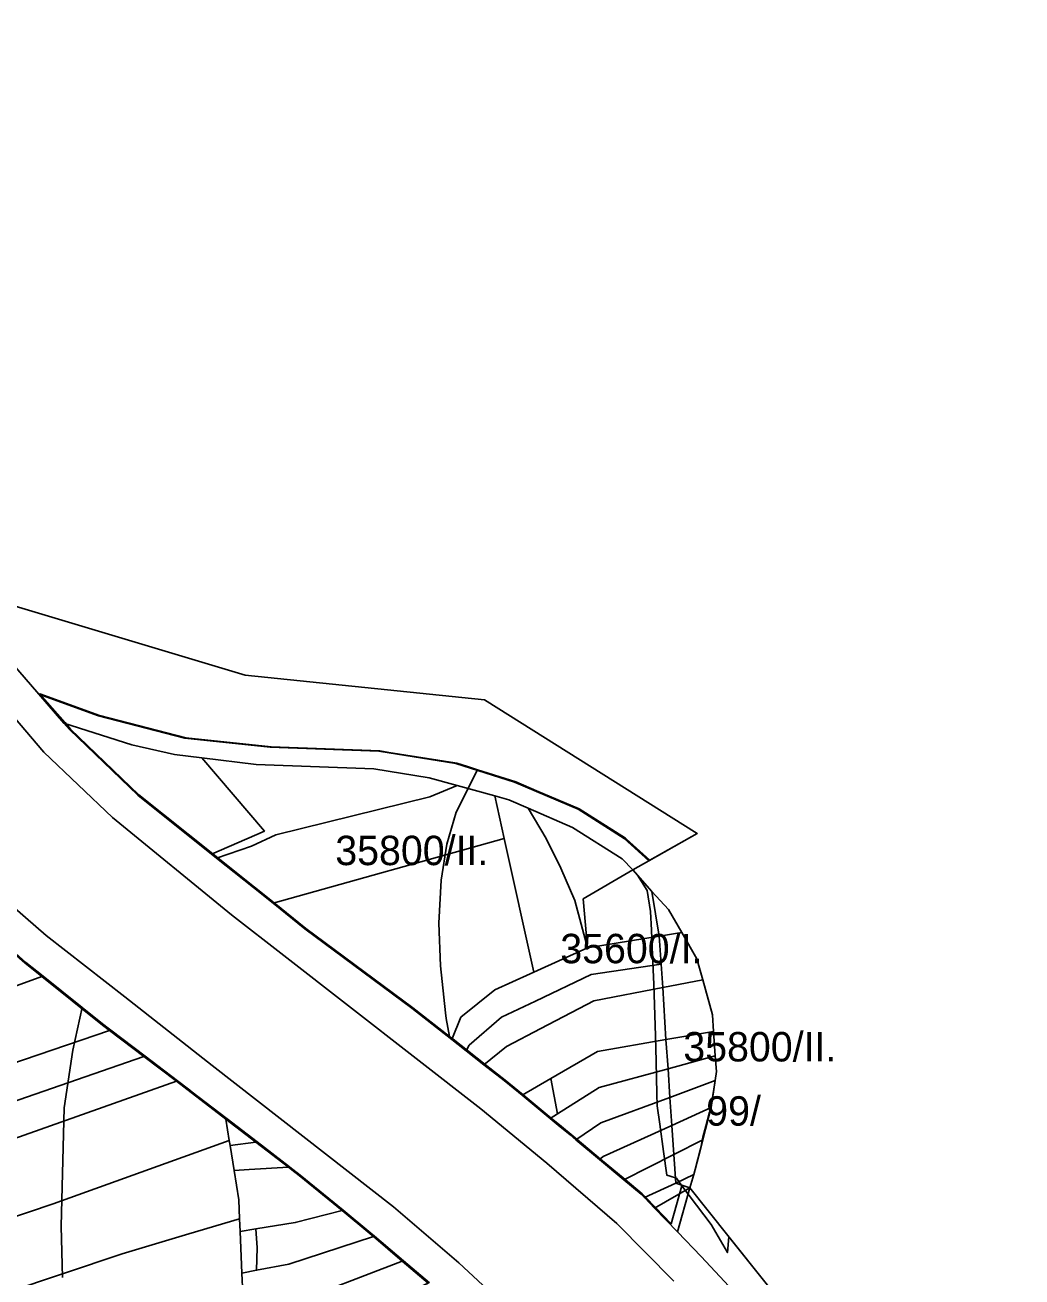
# Model space of a CAD drawing. Extents: x -535894 to -532827, y -1165802 to -1163635.
# Drawn here: x -533625 to -533117, y -1164507 to -1163869 of the extents above; entities that cross this region are included whole.
import ezdxf

# ---------------------------------------------------------------- set-up
doc = ezdxf.new("R2010")
doc.units = 0
for name, color, linetype in [('BPEJ_s', 7, 'Continuous'), ('orna_s', 7, 'Continuous'), ('ostatni_s', 7, 'Continuous'), ('trav_porost_s', 7, 'Continuous'), ('voda_s', 7, 'Continuous')]:
    doc.layers.add(name, color=color, linetype=linetype)

msp = doc.modelspace()

# ---------------------------------------------------------------- linework, layer by layer
at = {"layer": 'BPEJ_s'}
for points in [[(-533637.25, -1164163.31), (-533513.14, -1164200.59), (-533391.15, -1164213.21), (-533282.63, -1164281.27), (-533306.824, -1164294.927), (-533318.689, -1164284.23), (-533319.215, -1164283.756), (-533342.741, -1164268.774), (-533364.507, -1164259.557), (-533375.189, -1164255.034), (-533394.693, -1164248.828), (-533399.775, -1164247.211), (-533405.147, -1164245.502), (-533406.3, -1164245.318), (-533439.891, -1164239.947), (-533444.45, -1164239.218), (-533499.877, -1164237.155), (-533543.375, -1164232.587), (-533587.465, -1164221.122), (-533617.855, -1164210.054), (-533605.015, -1164224.773), (-533602.168, -1164228.037), (-533567.381, -1164261.637), (-533529.675, -1164291.688), (-533508.391, -1164308.653), (-533498.372, -1164316.72), (-533482.183, -1164329.739), (-533427.582, -1164370.261), (-533408.962, -1164384.837), (-533407.119, -1164386.28), (-533399.797, -1164392.005), (-533390.783, -1164399.064), (-533382.023, -1164405.923), (-533380.51, -1164407.108), (-533371.36, -1164414.666), (-533357.069, -1164426.477), (-533351.871, -1164430.767), (-533346.896, -1164434.883), (-533343.848, -1164437.415), (-533331.897, -1164447.377), (-533319.421, -1164457.779), (-533310.674, -1164465.071), (-533308.987, -1164466.818), (-533303.773, -1164472.227), (-533295.97, -1164480.319), (-533290.471, -1164460.99), (-533275.469, -1164480.798), (-533267.177, -1164495.052), (-533266.414, -1164486.957), (-533227.22, -1164536.15)], [(-533631.849, -1164340.954), (-533624.977, -1164347.111), (-533616.237, -1164354.099), (-533596.317, -1164370.019)], [(-533419.163, -1164510.425), (-533432.421, -1164499.181), (-533447.139, -1164486.688), (-533449.061, -1164485.066), (-533463.157, -1164473.487), (-533485.08, -1164455.484), (-533488.779, -1164452.648), (-533490.512, -1164451.319), (-533507.067, -1164438.601), (-533522.39, -1164426.846), (-533540.189, -1164413.195), (-533541.383, -1164412.285), (-533547.683, -1164407.482), (-533564.22, -1164394.878), (-533581.704, -1164381.564), (-533583.679, -1164380.059), (-533585.293, -1164378.83), (-533596.317, -1164370.019), (-533616.237, -1164354.099), (-533624.977, -1164347.111), (-533631.849, -1164340.954)], [(-533596.317, -1164370.019), (-533601.09, -1164391.8), (-533605.391, -1164421.259), (-533606.98, -1164481.63), (-533606.34, -1164507.75)], [(-533606.34, -1164507.75), (-533606.98, -1164481.63), (-533605.391, -1164421.259), (-533601.09, -1164391.8), (-533596.317, -1164370.019), (-533585.293, -1164378.83), (-533583.679, -1164380.059), (-533581.704, -1164381.564), (-533564.22, -1164394.878), (-533547.683, -1164407.482), (-533541.383, -1164412.285), (-533540.189, -1164413.195), (-533522.39, -1164426.846), (-533507.067, -1164438.601), (-533490.512, -1164451.319), (-533488.779, -1164452.648), (-533485.08, -1164455.484), (-533463.157, -1164473.487), (-533449.061, -1164485.066), (-533447.139, -1164486.688), (-533432.421, -1164499.181), (-533419.163, -1164510.425)]]:
    msp.add_lwpolyline(points, dxfattribs=at)
for points in [[(-533394.693, -1164248.828), (-533405.49, -1164270.43), (-533410.27, -1164286.67), (-533413.14, -1164305.15), (-533414.411, -1164326.97), (-533413.524, -1164348.809), (-533410.92, -1164372.686), (-533410.59, -1164375.71), (-533408.962, -1164384.837), (-533427.582, -1164370.261), (-533482.183, -1164329.739), (-533498.372, -1164316.72), (-533508.391, -1164308.653), (-533529.675, -1164291.688), (-533567.381, -1164261.637), (-533602.168, -1164228.037), (-533605.015, -1164224.773), (-533617.855, -1164210.054), (-533587.465, -1164221.122), (-533543.375, -1164232.587), (-533499.877, -1164237.155), (-533444.45, -1164239.218), (-533439.891, -1164239.947), (-533406.3, -1164245.318), (-533405.147, -1164245.502), (-533399.775, -1164247.211)], [(-533306.824, -1164294.927), (-533307.29, -1164295.19), (-533315.38, -1164299.76), (-533312.979, -1164302.529), (-533308.125, -1164310.332), (-533306.426, -1164321.014), (-533305.972, -1164330.592), (-533305.373, -1164343.305), (-533304.675, -1164358.111), (-533303.964, -1164384.558), (-533303.616, -1164397.625), (-533303.177, -1164414.033), (-533303.014, -1164420.167), (-533301.728, -1164429.587), (-533299.828, -1164443.44), (-533298.173, -1164455.526), (-533296.377, -1164456.108), (-533293.202, -1164457.145), (-533290.471, -1164460.99), (-533295.97, -1164480.319), (-533303.773, -1164472.227), (-533308.987, -1164466.818), (-533310.674, -1164465.071), (-533319.421, -1164457.779), (-533331.897, -1164447.377), (-533343.848, -1164437.415), (-533346.896, -1164434.883), (-533351.871, -1164430.767), (-533357.069, -1164426.477), (-533371.36, -1164414.666), (-533380.51, -1164407.108), (-533382.023, -1164405.923), (-533390.783, -1164399.064), (-533399.797, -1164392.005), (-533407.119, -1164386.28), (-533408.962, -1164384.837), (-533410.59, -1164375.71), (-533410.92, -1164372.686), (-533413.524, -1164348.809), (-533414.411, -1164326.97), (-533413.14, -1164305.15), (-533410.27, -1164286.67), (-533405.49, -1164270.43), (-533394.693, -1164248.828), (-533375.189, -1164255.034), (-533364.507, -1164259.557), (-533342.741, -1164268.774), (-533319.215, -1164283.756), (-533318.689, -1164284.23)], [(-533275.249, -1164419.367), (-533276.425, -1164423.386), (-533278.23, -1164430.56), (-533279.661, -1164436.105), (-533280.772, -1164441.617), (-533283.68, -1164452.7), (-533284.39, -1164455.19), (-533286.31, -1164461.99), (-533266.97, -1164486.26), (-533266.414, -1164486.957), (-533267.177, -1164495.052), (-533275.469, -1164480.798), (-533290.471, -1164460.99), (-533293.202, -1164457.145), (-533296.377, -1164456.108), (-533298.173, -1164455.526), (-533299.828, -1164443.44), (-533301.728, -1164429.587), (-533303.014, -1164420.167), (-533303.177, -1164414.033), (-533303.616, -1164397.625), (-533303.964, -1164384.558), (-533304.675, -1164358.111), (-533305.373, -1164343.305), (-533305.972, -1164330.592), (-533306.426, -1164321.014), (-533308.125, -1164310.332), (-533312.979, -1164302.529), (-533305.71, -1164310.91), (-533297.21, -1164320.14), (-533290.4, -1164331.87), (-533282.74, -1164345.28), (-533279.76, -1164355.99), (-533274.89, -1164373.76), (-533274.29, -1164382.26), (-533273.41, -1164394.65), (-533272.85, -1164402.66), (-533273.53, -1164407.35)], [(-533279.71, -1164437.57), (-533280.772, -1164441.617), (-533279.661, -1164436.105), (-533278.23, -1164430.56), (-533276.425, -1164423.386), (-533275.249, -1164419.367), (-533275.5, -1164421.12)]]:
    msp.add_lwpolyline(points, close=True, dxfattribs=at)
at = {"layer": 'orna_s'}
for points in [[(-533605.59, -1164224.96), (-533571.03, -1164236.07), (-533549.12, -1164240.98), (-533535.33, -1164242.69), (-533503.3, -1164280.07), (-533530.25, -1164291.87), (-533567.95, -1164261.82), (-533602.74, -1164228.22)], [(-533507.55, -1164246.14), (-533447.47, -1164248.27), (-533419.39, -1164252.85), (-533405.05, -1164256.81), (-533418.99, -1164262.66), (-533497.49, -1164281.99), (-533509.99, -1164287.71), (-533527.78, -1164293.84), (-533530.25, -1164291.87), (-533503.3, -1164280.07), (-533535.33, -1164242.69)], [(-533385.83, -1164262.11), (-533381.03, -1164283.8), (-533498.95, -1164316.9), (-533508.97, -1164308.83), (-533527.78, -1164293.84), (-533509.99, -1164287.71), (-533497.49, -1164281.99), (-533418.99, -1164262.66), (-533405.05, -1164256.81)], [(-533378.64, -1164264.1), (-533368.79, -1164268.38), (-533359.57, -1164283.78), (-533352.12, -1164299.01), (-533345.01, -1164315.49), (-533338.55, -1164339.54), (-533365.92, -1164351.97), (-533381.03, -1164283.8), (-533385.83, -1164262.11)], [(-533346.28, -1164278.18), (-533320.95, -1164294.31), (-533315.38, -1164299.76), (-533340.84, -1164314.67), (-533338.55, -1164339.54), (-533345.01, -1164315.49), (-533352.12, -1164299.01), (-533359.57, -1164283.78), (-533368.79, -1164268.38)], [(-533498.95, -1164316.9), (-533381.03, -1164283.8), (-533365.92, -1164351.97), (-533367.81, -1164352.83), (-533385.8, -1164361), (-533403.21, -1164375.02), (-533407.7, -1164386.45), (-533428.16, -1164370.44), (-533482.76, -1164329.92)], [(-533305.71, -1164310.91), (-533302.09, -1164333.74), (-533338.55, -1164339.54), (-533340.84, -1164314.67), (-533315.38, -1164299.76)], [(-533305.71, -1164310.91), (-533297.21, -1164320.14), (-533290.4, -1164331.87), (-533302.09, -1164333.74)], [(-533338.55, -1164339.54), (-533302.09, -1164333.74), (-533300.97, -1164347.97), (-533336.72, -1164353.24), (-533365.08, -1164366.74), (-533382.4, -1164374.97), (-533398.87, -1164389.28), (-533400.38, -1164392.18), (-533407.7, -1164386.45), (-533403.21, -1164375.02), (-533385.8, -1164361), (-533367.81, -1164352.83), (-533365.92, -1164351.97)], [(-533302.09, -1164333.74), (-533290.4, -1164331.87), (-533282.74, -1164345.28), (-533279.76, -1164355.99), (-533300.16, -1164359.88), (-533300.97, -1164347.97)], [(-533632.43, -1164341.14), (-533625.55, -1164347.3), (-533616.81, -1164354.28), (-533723.42, -1164393.06), (-533771.52, -1164411.45), (-533810.55, -1164423.74), (-533962.73, -1164479.54), (-533965.5, -1164468.47), (-533967.42, -1164462.17), (-533868.12, -1164425.2)], [(-533336.72, -1164353.24), (-533300.97, -1164347.97), (-533300.16, -1164359.88), (-533335.3, -1164366.6), (-533362.32, -1164380.78), (-533379.89, -1164389.99), (-533391.36, -1164399.24), (-533400.38, -1164392.18), (-533398.87, -1164389.28), (-533382.4, -1164374.97), (-533365.08, -1164366.74)], [(-533616.81, -1164354.28), (-533585.87, -1164379.01), (-533582.28, -1164381.75), (-533655.23, -1164406.66), (-533798.86, -1164459.07), (-533954.44, -1164514.16), (-533955.24, -1164509.41), (-533962.73, -1164479.54), (-533810.55, -1164423.74), (-533771.52, -1164411.45), (-533723.42, -1164393.06)], [(-533335.3, -1164366.6), (-533300.16, -1164359.88), (-533298.54, -1164386.42), (-533333.5, -1164392.41), (-533357.3, -1164406.29), (-533371.94, -1164414.84), (-533381.09, -1164407.28), (-533391.36, -1164399.24), (-533379.89, -1164389.99), (-533362.32, -1164380.78)], [(-533300.16, -1164359.88), (-533279.76, -1164355.99), (-533274.89, -1164373.76), (-533274.29, -1164382.26), (-533298.54, -1164386.42)], [(-533582.28, -1164381.75), (-533564.8, -1164395.06), (-533671.49, -1164431.9), (-533847.42, -1164496.13), (-533951.43, -1164531.95), (-533954.44, -1164514.16), (-533798.86, -1164459.07), (-533655.23, -1164406.66)], [(-533298.54, -1164386.42), (-533274.29, -1164382.26), (-533273.41, -1164394.65), (-533297.5, -1164401.27)], [(-533333.5, -1164392.41), (-533298.54, -1164386.42), (-533297.5, -1164401.27), (-533332.56, -1164410.91), (-533353.78, -1164424.22), (-533357.3, -1164406.29)], [(-533564.8, -1164395.06), (-533548.26, -1164407.66), (-533732.91, -1164473.02), (-533829.26, -1164508.78), (-533948.58, -1164548.78), (-533951.43, -1164531.95), (-533847.42, -1164496.13), (-533671.49, -1164431.9)], [(-533297.5, -1164401.27), (-533273.41, -1164394.65), (-533272.85, -1164402.66), (-533273.53, -1164407.35), (-533296.57, -1164415.9)], [(-533332.56, -1164410.91), (-533297.5, -1164401.27), (-533296.57, -1164415.9), (-533331.75, -1164428.95), (-533344.43, -1164437.59), (-533347.48, -1164435.05), (-533352.45, -1164430.94), (-533357.65, -1164426.65), (-533353.78, -1164424.22)], [(-533548.26, -1164407.66), (-533540.77, -1164413.38), (-533522.97, -1164427.03), (-533521.25, -1164437.9), (-533611.16, -1164470.19), (-533698.34, -1164499.57), (-533834.24, -1164549.38), (-533941.27, -1164585.42), (-533948.58, -1164548.78), (-533829.26, -1164508.78), (-533732.91, -1164473.02)], [(-533371.94, -1164414.84), (-533357.3, -1164406.29), (-533353.78, -1164424.22), (-533357.65, -1164426.65)], [(-533296.57, -1164415.9), (-533273.53, -1164407.35), (-533275.5, -1164421.12), (-533295.61, -1164430.22)], [(-533331.75, -1164428.95), (-533296.57, -1164415.9), (-533295.61, -1164430.22), (-533330.63, -1164446.04), (-533332.48, -1164447.55), (-533344.43, -1164437.59)], [(-533295.61, -1164430.22), (-533275.5, -1164421.12), (-533279.71, -1164437.57), (-533294.57, -1164445.09)], [(-533521.25, -1164437.9), (-533522.97, -1164427.03), (-533507.65, -1164438.78), (-533520.85, -1164440.43)], [(-533295.61, -1164430.22), (-533294.57, -1164445.09), (-533320, -1164457.95), (-533332.48, -1164447.55), (-533330.63, -1164446.04)], [(-533520.85, -1164440.43), (-533518.84, -1164453.12), (-533516.47, -1164468.06), (-533516.03, -1164477.8), (-533541.84, -1164485.53), (-533575.81, -1164495.71), (-533694.14, -1164535.35), (-533849.54, -1164592.24), (-533906.52, -1164610.42), (-533945.61, -1164619.41), (-533941.56, -1164587.64), (-533941.27, -1164585.42), (-533834.24, -1164549.38), (-533698.34, -1164499.57), (-533611.16, -1164470.19), (-533521.25, -1164437.9)], [(-533520.85, -1164440.43), (-533507.65, -1164438.78), (-533491.1, -1164451.5), (-533511.14, -1164452.67), (-533518.84, -1164453.12)], [(-533294.57, -1164445.09), (-533279.71, -1164437.57), (-533283.68, -1164452.7), (-533284.39, -1164455.19), (-533293.51, -1164459.56)], [(-533320, -1164457.95), (-533294.57, -1164445.09), (-533293.51, -1164459.56), (-533309.57, -1164466.99), (-533311.26, -1164465.24)], [(-533511.14, -1164452.67), (-533491.1, -1164451.5), (-533489.36, -1164452.83), (-533485.66, -1164455.66), (-533463.74, -1164473.66), (-533487.58, -1164479.72), (-533507.75, -1164482.99), (-533515.75, -1164484.29), (-533516.03, -1164477.8), (-533516.47, -1164468.06), (-533518.84, -1164453.12)], [(-533293.51, -1164459.56), (-533284.39, -1164455.19), (-533286.31, -1164461.99)], [(-533293.51, -1164459.56), (-533286.31, -1164461.99), (-533304.36, -1164472.39), (-533309.57, -1164466.99)], [(-533304.36, -1164472.39), (-533286.31, -1164461.99), (-533292.65, -1164484.53)], [(-533487.58, -1164479.72), (-533463.74, -1164473.66), (-533449.65, -1164485.24), (-533447.72, -1164486.86), (-533490.83, -1164500.89), (-533507.3, -1164504.04), (-533507.02, -1164492.54), (-533507.75, -1164482.99)], [(-533515.75, -1164484.29), (-533514.81, -1164505.48), (-533514.33, -1164516.05), (-533539.69, -1164523.07), (-533562.86, -1164529.48), (-533603.27, -1164541.66), (-533709.08, -1164577.64), (-533811.93, -1164617.39), (-533884.44, -1164639.64), (-533944.79, -1164655.52), (-533945.09, -1164650.16), (-533945.65, -1164648.02), (-533949.17, -1164647.34), (-533948.72, -1164643.84), (-533945.61, -1164619.41), (-533906.52, -1164610.42), (-533849.54, -1164592.24), (-533694.14, -1164535.35), (-533575.81, -1164495.71), (-533541.84, -1164485.53), (-533516.03, -1164477.8)], [(-533515.75, -1164484.29), (-533507.75, -1164482.99), (-533507.02, -1164492.54), (-533507.3, -1164504.04), (-533514.81, -1164505.48)], [(-533447.72, -1164486.86), (-533433.01, -1164499.36), (-533492.42, -1164522.13), (-533506.35, -1164525.6), (-533512.72, -1164527.18), (-533514.33, -1164516.05), (-533514.81, -1164505.48), (-533507.3, -1164504.04), (-533490.83, -1164500.89)], [(-533433.01, -1164499.36), (-533419.75, -1164510.6), (-533455.4, -1164526.78), (-533503.24, -1164545.82), (-533509.63, -1164548.37), (-533511.85, -1164533.08), (-533512.72, -1164527.18), (-533506.35, -1164525.6), (-533492.42, -1164522.13)]]:
    msp.add_lwpolyline(points, close=True, dxfattribs=at)
at = {"layer": 'ostatni_s'}
for points in [[(-533853.53, -1163871.16), (-533852.38, -1163870.19), (-533852.91, -1163873.85), (-533850.38, -1163873.16), (-533835.15, -1163868.99), (-533835.25, -1163876.86), (-533832.51, -1163912.75), (-533831.47, -1163958.19), (-533821.43, -1163999.88), (-533807.37, -1164047.78), (-533785.98, -1164100.6), (-533771.58, -1164135.97), (-533760.11, -1164157.23), (-533736.29, -1164196.18), (-533708.99, -1164234.05), (-533688.28, -1164260.76), (-533659.7, -1164292.03), (-533637.12, -1164313.74), (-533614.65, -1164333.34), (-533574.57, -1164364.55), (-533529.97, -1164399.56), (-533437.52, -1164471.63), (-533404.17, -1164500.26), (-533365.03, -1164536.67)], [(-533640.06, -1164185.46), (-533618.43, -1164210.24), (-533605.59, -1164224.96), (-533602.74, -1164228.22), (-533567.95, -1164261.82), (-533530.25, -1164291.87), (-533527.78, -1164293.84), (-533508.97, -1164308.83), (-533498.95, -1164316.9), (-533482.76, -1164329.92), (-533428.16, -1164370.44), (-533407.7, -1164386.45), (-533400.38, -1164392.18), (-533391.36, -1164399.24), (-533381.09, -1164407.28), (-533371.94, -1164414.84), (-533357.65, -1164426.65), (-533352.45, -1164430.94), (-533347.48, -1164435.05), (-533344.43, -1164437.59), (-533332.48, -1164447.55), (-533320, -1164457.95), (-533311.26, -1164465.24), (-533309.57, -1164466.99), (-533304.36, -1164472.39), (-533292.65, -1164484.53), (-533280.62, -1164497.03), (-533235.68, -1164545.17)], [(-533294.45, -1164509.67), (-533323.6, -1164480.19), (-533359.31, -1164449.39), (-533393.01, -1164421.73), (-533493.52, -1164343.51), (-533520.08, -1164322.87), (-533580.88, -1164273.2), (-533615.89, -1164239.81), (-533652.75, -1164196.64)], [(-533564.8, -1164395.06), (-533582.28, -1164381.75), (-533585.87, -1164379.01), (-533616.81, -1164354.28), (-533625.55, -1164347.3)], [(-533419.75, -1164510.6), (-533433.01, -1164499.36), (-533447.72, -1164486.86), (-533449.65, -1164485.24), (-533463.74, -1164473.66), (-533485.66, -1164455.66), (-533489.36, -1164452.83), (-533491.1, -1164451.5), (-533507.65, -1164438.78), (-533522.97, -1164427.03), (-533540.77, -1164413.38), (-533548.26, -1164407.66), (-533564.8, -1164395.06)]]:
    msp.add_lwpolyline(points, dxfattribs=at)
msp.add_lwpolyline([(-533286.31, -1164461.99), (-533266.97, -1164486.26), (-533227.22, -1164536.15), (-533217.69, -1164548.05), (-533212.4, -1164563.33), (-533202.85, -1164583.35), (-533177.04, -1164603.82), (-533165.64, -1164607.65), (-533127.31, -1164620.51), (-533116.98, -1164633.6), (-533177.92, -1164613.75), (-533205.86, -1164580.27), (-533235.68, -1164545.17), (-533280.62, -1164497.03), (-533292.65, -1164484.53)], close=True, dxfattribs=at)
at = {"layer": 'trav_porost_s'}
msp.add_lwpolyline([(-533588.04, -1164221.3), (-533543.95, -1164232.77), (-533500.45, -1164237.33), (-533445.02, -1164239.39), (-533405.72, -1164245.67), (-533375.76, -1164255.2), (-533343.32, -1164268.94), (-533319.79, -1164283.92), (-533307.29, -1164295.19), (-533315.38, -1164299.76), (-533320.95, -1164294.31), (-533346.28, -1164278.18), (-533368.79, -1164268.38), (-533378.64, -1164264.1), (-533385.83, -1164262.11), (-533405.05, -1164256.81), (-533419.39, -1164252.85), (-533447.47, -1164248.27), (-533507.55, -1164246.14), (-533535.33, -1164242.69), (-533549.12, -1164240.98), (-533571.03, -1164236.07), (-533605.59, -1164224.96), (-533618.43, -1164210.24)], close=True, dxfattribs=at)
at = {"layer": 'voda_s'}
msp.add_lwpolyline([(-533663.1, -1164153.72), (-533678.92, -1164127.1), (-533637.25, -1164163.31), (-533513.14, -1164200.59), (-533391.15, -1164213.21), (-533282.63, -1164281.27), (-533307.29, -1164295.19), (-533319.79, -1164283.92), (-533343.32, -1164268.94), (-533375.76, -1164255.2), (-533405.72, -1164245.67), (-533445.02, -1164239.39), (-533500.45, -1164237.33), (-533543.95, -1164232.77), (-533588.04, -1164221.3), (-533618.43, -1164210.24), (-533640.06, -1164185.46)], close=True, dxfattribs=at)
for points in [[(-533652.75, -1164196.64), (-533615.89, -1164239.81), (-533580.88, -1164273.2), (-533520.08, -1164322.87), (-533493.52, -1164343.51), (-533393.01, -1164421.73), (-533359.31, -1164449.39), (-533323.6, -1164480.19), (-533294.45, -1164509.67)], [(-533365.03, -1164536.67), (-533404.17, -1164500.26), (-533437.52, -1164471.63), (-533529.97, -1164399.56), (-533574.57, -1164364.55), (-533614.65, -1164333.34), (-533637.12, -1164313.74)]]:
    msp.add_lwpolyline(points, dxfattribs=at)

# ---------------------------------------------------------------- texts
at = {"layer": 'BPEJ_s'}
for s, p in [('35800/II.', (-533467.198, -1164297.446)), ('35600/I.', (-533352.441, -1164347.482)), ('35800/II.', (-533289.697, -1164397.557)), ('99/', (-533278.011, -1164430.309))]:
    msp.add_text(s, height=15, dxfattribs=at).set_placement(p)

doc.saveas('drawing.dxf')
